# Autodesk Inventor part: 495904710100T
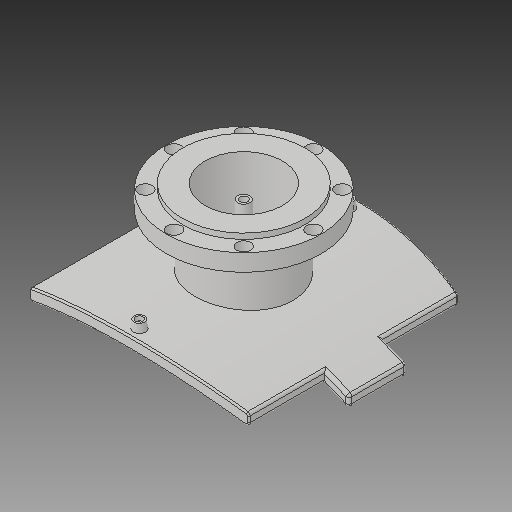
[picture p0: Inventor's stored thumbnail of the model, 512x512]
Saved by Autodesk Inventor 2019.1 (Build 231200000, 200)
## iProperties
Created: 2017-10
Part Number: 495904710100T
Material: Generic
Description: PLASSON FLANGED BRANCH SADDLE 450-800X100
Document SubType Name: Modeling
Designer: KIM
Mass: 2339.99 g
Surface Area: 3251.55 cm^2
Volume: 2339.99 cm^3
Density: 1 g/cm^3
Appearance: Default
Author: KIM
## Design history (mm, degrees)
derived "495904_495903.ipt"
feature "Solid1::495904_495903.ipt"
feature "Solid2::495904_495903.ipt"
tag "TaggingFeature1"
body "Solid1"
other parameters: "d1" = 15, "d2" = 283.5, "d4" = 0, "d6" = 75, "d7" = 0, "d11" = 4, "d12" = 425.6, "d13" = 14, "d14" = 135, "d16" = 5 deg, "d18" = 4, "d19" = 14, "d20" = 0, "d21" = 3, "d22" = 0, "d23" = 525, "d36" = 135, "d38" = 0, "d39" = 2, "d42" = 158, "d44" = 88, "d46" = 126.4, "d47" = 16, "d48" = 10.4, "d49" = 77, "d51" = 816, "d53" = 0, "d54" = 18, "d57" = 0, "d59" = 360 deg, "d61" = 22, "d63" = 0, "d65" = 315, "d_1" = 158, "B_" = 315, "x_" = 15, "D_" = 16, "t_" = 22, "s_" = 18
